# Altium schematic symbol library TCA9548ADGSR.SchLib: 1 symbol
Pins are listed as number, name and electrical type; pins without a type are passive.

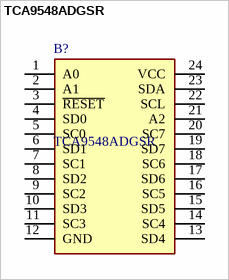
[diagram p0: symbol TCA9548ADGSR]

## TCA9548ADGSR
designator B?
Switch ICs - Various 8-channel 1.65- to 5 .5-V I2C/SMBus switc; Manufacturer_Name: Texas Instruments; Geometry.Height: 1.1mm
footprint SOP50P490X110-24N
pins: 1 A0, 2 A1, 3 ~{RESET}, 4 SD0, 5 SC0, 6 SD1, 7 SC1, 8 SD2, 9 SC2, 10 SD3, 11 SC3, 12 GND, 13 SD4, 14 SC4, 15 SD5, 16 SC5, 17 SD6, 18 SC6, 19 SD7, 20 SC7, 21 A2, 22 SCL, 23 SDA, 24 VCC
